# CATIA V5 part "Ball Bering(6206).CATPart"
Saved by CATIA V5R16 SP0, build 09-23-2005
Part number: Ball Bering(6206)
Bounding box of the stored display mesh (mm): x -31 to 31, y -8 to 8, z -31 to 31
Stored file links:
  C:\V5_education\CATIA Data\ASD\Power Transmission Gear Assembly\Assembly Data\Ball Bering(6206).CATPart
  C:\Program Files\Dassault Systemes\B20\win_b64\startup\materials\Catalog.CATMaterial
  D:\#10 Work\#01 CATIA Lecture Materials\#03 Bearing Template\#02 Document\Ball Bearing DesignTable.xls
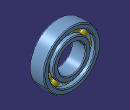
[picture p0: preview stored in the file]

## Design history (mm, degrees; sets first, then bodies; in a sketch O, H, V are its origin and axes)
External parameters (linked from other documents)
  External.D = 62 mm
  External.d = 30 mm
  External.B = 16 mm
  External.r = 0.975 mm
  External.s = 4.16 mm {= (External.D -External.d )*0.13}
  External.Z = 12 {= int((External.D + External.d ) / (External.s * 2) ) +1}
  `External.Bearing Number` = "6206"
Set1 "Reference Data"
  Point1 "Center Point": (0, 0, 0)
  Point2: (0, 0, 23 {= (External.D+External.d)/4}), relative to Point1
  Sphere1 "Ball": Center Point2, Radius 4.16 {= External.s}, Angle1 -45, Angle3 0, Angle4 180
Body1 "PartBody" (main body)
  Body2 "Body.1"
    Sketch1 on xy-plane, origin (0, 0, 0), H (1, 0, 0), V (0, 1, 0)
      axis line L1 (0, 0) -> (0, 87.7764)
      construction line L2 (23, 0) -> (23, 15.0879)
      point P2 (23, 0)
      line L3 (15, 8) -> (31, 8)
      line L4 (31, 8) -> (31, -8)
      line L5 (31, -8) -> (15, -8)
      line L6 (15, -8) -> (15, 8)
      distance L3 L5 = 16 {= External.B}
      distance L1 L6 = 15 {= External.d /2}
      distance L1 L4 = 31 {= External.D /2}
      vertical: L1 V, L2 V, L4 V, L6 V
      coincidence: P2 H
      horizontal: L3 H, L5 H
      symmetry: L6 L4 L2, L3 L5 H
    Shaft1: profile Sketch1, axis Sketch1.L1, angle 360
    Sketch2 on xy-plane, origin (0, 0, 0), H (1, 0, 0), V (0, 1, 0)
      axis line L1 (0, 0) -> (0, 17.8821)
      line L2 (20.6, 8) -> (25.4, 8)
      line L3 (25.4, 8) -> (25.4, 3.3979)
      line L4 (25.4, -8) -> (20.6, -8)
      line L5 (20.6, -8) -> (20.6, -3.3979)
      arc A1 centre (23, 0) radius 4.16 from (20.6, 3.3979) to (20.6, -3.3979) ccw
      point P6 (23, 0)
      construction line L6 (23, 0) -> (23, 8)
      point P7 (23, 8)
      point P8 (25.4, -3.3979)
      line L7 (25.4, -3.3979) -> (25.4, -8)
      point P10 (20.6, 3.3979)
      line L8 (20.6, 3.3979) -> (20.6, 8)
      arc A2 centre (23, 0) radius 4.16 from (25.4, -3.3979) to (25.4, 3.3979) ccw
      distance L5 L3 = 4.8 {= (External.D - External.d) * 0.15}
      radius A1 = 4.16 {= External.s}
      distance L2 L4 = 16 {= External.B}
      distance L6 L1 = 23 {= Point2.Z}
      vertical: L1 V, L3 V, L5 V, L6 V, L7 V, L8 V
      horizontal: L2 H, L4 H
      coincidence: P6 H, A1 P8, L3 L7, L5 P10, L5 L8, A1 A2
      midpoint: P7 L2
      symmetry: L5 L3 L6, L2 L4 H
    Groove1: profile Sketch2, axis Sketch2.L1, angle 360
    Fillet1: radius 0.975 {= External.r}, on face of Shaft1 from Sketch1.L4; edge [face of Shaft1 from Sketch1.L6 | face of Shaft1 from Sketch1.L5]; edge [face of Shaft1 from Sketch1.L3 | face of Shaft1 from Sketch1.L6]; edge [face of Groove1 from Sketch2.L7 | face of Shaft1 from Sketch1.L5]; edge [face of Shaft1 from Sketch1.L5 | face of Groove1 from Sketch2.L5]; edge [face of Shaft1 from Sketch1.L3 | face of Groove1 from Sketch2.L3]; edge [face of Groove1 from Sketch2.L8 | face of Shaft1 from Sketch1.L3]
  Assemble1: tool Body2
  Body3
    CloseSurface1: CloseElement Sphere1
    CircPattern1: of the body so far, instances 12 {= External.Z}, angular step 30 {= 360.0*1 deg/CircPattern1.AngularNumber}, axis from zx-plane
  Assemble2: tool Body3
Relations
  rule:
    if `External.Bearing Number` =="6200"
    	{
    		External.D = 30mm
    		External.d = 10mm
    		External.B = 9mm
    		External.r = 0.61mm
    	}
    else if `External.Bearing Number` =="6201"
    	{
    		External.D = 32mm
    		External.d = 12mm
    		External.B = 10mm
    		External.r = 0.61mm
    	}
    else if `External.Bearing Number` =="6202"
    	{
    		External.D = 35mm
    		External.d = 15mm
    		External.B = 11mm
    		External.r = 0.61mm
    	}
    else if `External.Bearing Number` =="6203"
    	{
    		External.D = 40mm
    		External.d = 17mm
    		External.B = 12mm
    		External.r = 0.61mm
    	}
    else if `External.Bearing Number` =="6204"
    	{
    		External.D = 47mm
    		External.d = 20mm
    		External.B = 14mm
    		External.r = 0.975mm
    	}
    else if `External.Bearing Number` =="6205"
    	{
    		External.D = 52mm
    		External.d = 25mm
    		External.B = 15mm
    		External.r = 0.975mm
    	}
    else if `External.Bearing Number` =="6206"
    	{
    		External.D = 62mm
    		External.d = 30mm
    		External.B = 16mm
    		External.r = 0.975mm
    	}
    else if `External.Bearing Number` =="6207"
    	{
    		External.D = 72mm
    		External.d = 35mm
    		External.B = 17mm
    		External.r = 0.975mm
    	}
    else if `External.Bearing Number` =="6208"
    	{
    		External.D = 80mm
    		External.d = 40mm
    		External.B = 18mm
    		External.r = 0.975mm
    	}
    else if `External.Bearing Number` =="6209"
    	{
    		External.D = 85mm
    		External.d = 45mm
    		External.B = 19mm
    		External.r = 0.975mm
    	}
    else
    	{
    		External.D = 90mm
    		External.d = 50mm
    		External.B = 20mm
    		External.r = 0.975mm
    	}
  design table "Ball Bearing Design Table", configuration 1, drives `External.Bearing Number`, External.D, External.d, External.B, External.r (deactivated)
